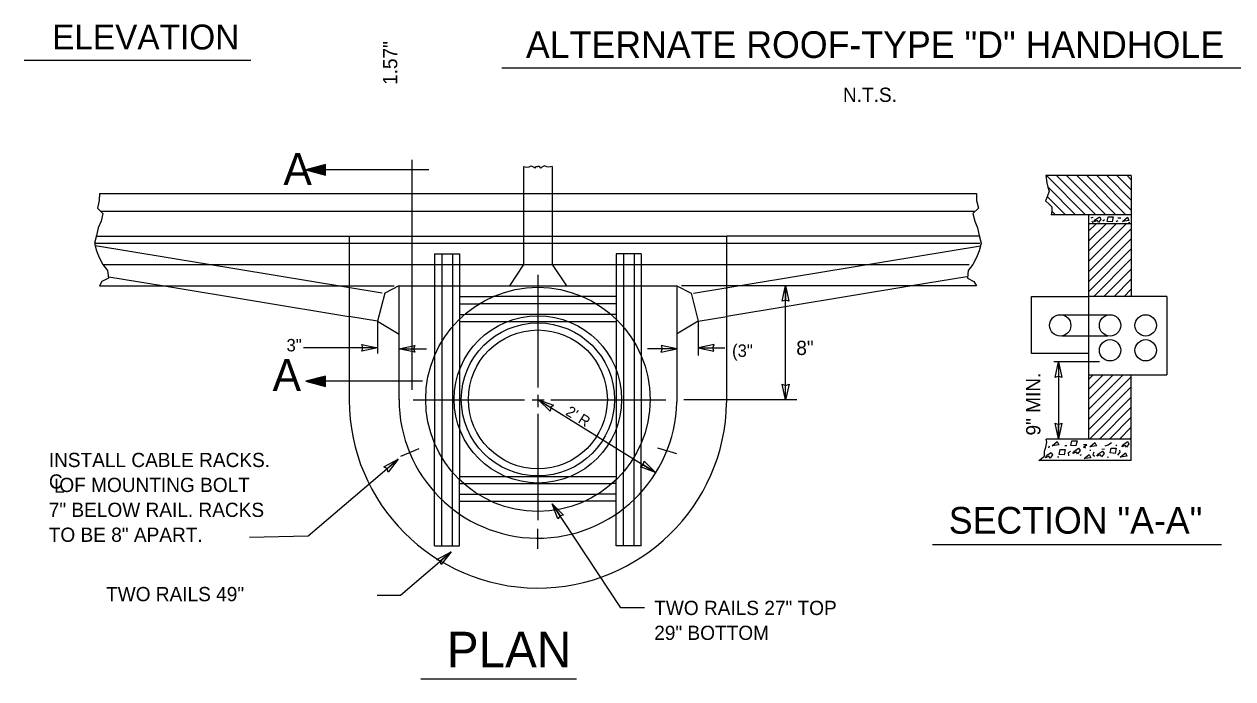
# Model space of a CAD drawing. Extents: x 19188 to 19495, y 20866 to 21061.
# Drawn here: x 19296.4 to 19367.5, y 20974.8 to 21013.4 of the extents above; entities that cross this region are included whole.
import ezdxf

# ---------------------------------------------------------------- set-up
doc = ezdxf.new("R2010")
doc.units = 0
doc.layers.add('G-ANNO-NOTE', color=7, linetype='Continuous')

msp = doc.modelspace()

# ---------------------------------------------------------------- linework, layer by layer
at = {"layer": 'G-ANNO-NOTE'}
for p, q in [((19296.432, 21011.256), (19309.768, 21011.256)), ((19324.516, 21010.791), (19369.32, 21010.791)), ((19319.253, 20991.839), (19319.253, 21005.377)), ((19320.227, 21004.804), (19313.006, 21004.804)), ((19314.124, 21004.55), (19314.124, 21005.015)), ((19325.807, 21005.001), (19325.807, 20999.217)), ((19327.483, 21005.001), (19327.483, 20999.217)), ((19361.548, 21004.454), (19356.52, 21004.454)), ((19356.557, 21004.454), (19358.861, 21002.149)), ((19357.149, 21004.454), (19359.454, 21002.149)), ((19357.742, 21004.454), (19360.046, 21002.149)), ((19358.335, 21004.454), (19360.639, 21002.149)), ((19358.927, 21004.454), (19361.231, 21002.149)), ((19359.52, 21004.454), (19361.548, 21002.425)), ((19360.112, 21004.454), (19361.548, 21003.018)), ((19360.704, 21004.454), (19361.548, 21003.61)), ((19361.297, 21004.454), (19361.548, 21004.202)), ((19361.548, 21004.454), (19361.548, 20997.331)), ((19300.854, 21003.406), (19352.435, 21003.406)), ((19356.595, 21003.231), (19357.676, 21002.149)), ((19356.649, 21003.769), (19358.269, 21002.149)), ((19300.961, 21002.359), (19352.321, 21002.359)), ((19361.548, 21002.149), (19356.825, 21002.149)), ((19356.871, 21002.362), (19357.084, 21002.149)), ((19359.034, 21002.149), (19359.034, 20988.953)), ((19359.192, 21001.98), (19359.313, 21002.008)), ((19359.223, 21001.786), (19359.282, 21001.674)), ((19359.343, 21001.73), (19359.432, 21001.869)), ((19359.552, 21001.813), (19359.343, 21001.73)), ((19359.432, 21001.869), (19359.672, 21002.036)), ((19359.612, 21001.702), (19359.552, 21001.813)), ((19359.762, 21001.897), (19359.612, 21001.702)), ((19359.672, 21002.036), (19359.762, 21001.897)), ((19359.882, 21001.786), (19359.972, 21001.869)), ((19360.122, 21001.758), (19360.181, 21002.036)), ((19360.421, 21001.73), (19360.122, 21001.758)), ((19360.181, 21002.036), (19360.481, 21002.036)), ((19360.481, 21002.036), (19360.421, 21001.73)), ((19360.661, 21001.758), (19360.751, 21001.813)), ((19360.751, 21001.98), (19360.93, 21001.98)), ((19361.02, 21001.758), (19361.32, 21002.008)), ((19361.41, 21001.813), (19361.02, 21001.758)), ((19361.32, 21002.008), (19361.41, 21001.813)), ((19361.38, 21001.702), (19361.47, 21001.702)), ((19361.548, 21001.626), (19359.034, 21001.626)), ((19359.035, 21001.183), (19359.477, 21001.626)), ((19359.037, 21000.593), (19360.07, 21001.626)), ((19359.038, 21000.001), (19360.662, 21001.626)), ((19359.039, 20999.41), (19361.254, 21001.626)), ((19359.04, 20998.819), (19361.548, 21001.326)), ((19300.601, 21000.474), (19352.63, 21000.474)), ((19317.485, 20997.539), (19300.621, 21000.325)), ((19300.696, 21000.893), (19315.529, 21000.893)), ((19315.543, 21000.893), (19315.543, 20991.257)), ((19315.543, 21000.893), (19337.746, 21000.893)), ((19335.804, 20997.539), (19352.668, 21000.325)), ((19337.746, 21000.893), (19337.746, 20991.106)), ((19352.593, 21000.893), (19337.761, 21000.893)), ((19359.042, 20998.228), (19361.548, 21000.734)), ((19320.57, 20999.846), (19320.57, 20993.853)), ((19320.57, 20999.846), (19322.036, 20999.846)), ((19320.989, 20999.846), (19320.989, 20994.689)), ((19321.618, 20999.846), (19321.618, 20995.543)), ((19322.036, 20999.846), (19322.036, 20995.988)), ((19332.719, 20999.846), (19331.253, 20999.846)), ((19331.253, 20999.846), (19331.253, 20995.988)), ((19331.672, 20999.846), (19331.672, 20995.524)), ((19332.3, 20999.846), (19332.3, 20994.651)), ((19332.719, 20999.846), (19332.719, 20993.816)), ((19359.043, 20997.637), (19361.548, 21000.141)), ((19359.322, 20997.323), (19361.548, 20999.549)), ((19301.08, 20999.217), (19352.013, 20999.217)), ((19325.807, 20999.217), (19324.969, 20997.96)), ((19327.483, 20999.217), (19328.321, 20997.96)), ((19359.916, 20997.325), (19361.548, 20998.956)), ((19301.42, 20998.495), (19304.66, 20997.96)), ((19351.87, 20998.495), (19348.629, 20997.96)), ((19360.511, 20997.327), (19361.548, 20998.364)), ((19300.854, 20997.96), (19318.198, 20997.96)), ((19304.658, 20997.96), (19315.524, 20996.165)), ((19317.638, 20997.541), (19317.212, 20995.886)), ((19318.476, 20997.96), (19317.638, 20997.541)), ((19318.476, 20997.96), (19318.476, 20991.257)), ((19318.476, 20997.96), (19334.814, 20997.96)), ((19334.814, 20997.96), (19335.652, 20997.541)), ((19334.814, 20997.96), (19334.814, 20991.131)), ((19352.435, 20997.96), (19335.091, 20997.96)), ((19335.652, 20997.541), (19336.078, 20995.886)), ((19348.631, 20997.96), (19337.765, 20996.165)), ((19341.212, 20991.257), (19341.212, 20997.987)), ((19341.212, 20997.987), (19341.212, 20997.134)), ((19361.106, 20997.33), (19361.548, 20997.772)), ((19322.036, 20997.332), (19324.018, 20997.332)), ((19322.036, 20996.913), (19323.197, 20996.913)), ((19330.059, 20996.913), (19323.197, 20996.913)), ((19329.299, 20997.332), (19324.018, 20997.332)), ((19331.253, 20997.332), (19329.299, 20997.332)), ((19331.253, 20996.913), (19330.079, 20996.913)), ((19355.682, 20993.98), (19355.682, 20997.331)), ((19355.682, 20997.331), (19359.043, 20997.331)), ((19363.642, 20997.331), (19359.043, 20997.331)), ((19363.642, 20997.331), (19363.642, 20992.723)), ((19317.212, 20995.886), (19315.533, 20996.163)), ((19322.036, 20996.284), (19322.317, 20996.284)), ((19322.036, 20995.988), (19322.036, 20986.556)), ((19330.919, 20996.284), (19322.357, 20996.284)), ((19331.253, 20996.284), (19330.919, 20996.284)), ((19331.253, 20995.988), (19331.253, 20986.574)), ((19336.078, 20995.886), (19337.756, 20996.163)), ((19357.454, 20996.257), (19360.15, 20996.257)), ((19317.212, 20995.886), (19318.489, 20995.132)), ((19317.212, 20995.886), (19317.212, 20993.984)), ((19321.618, 20995.543), (19321.618, 20987.02)), ((19322.036, 20995.866), (19331.253, 20995.866)), ((19331.672, 20995.524), (19331.672, 20987.001)), ((19336.078, 20995.886), (19334.801, 20995.132)), ((19336.078, 20995.886), (19336.078, 20993.867)), ((19320.989, 20994.689), (19320.989, 20987.892)), ((19332.3, 20994.651), (19332.3, 20987.855)), ((19357.468, 20995.022), (19360.176, 20995.022)), ((19317.212, 20994.318), (19312.868, 20994.318)), ((19317.212, 20994.318), (19316.359, 20994.318)), ((19318.476, 20994.268), (19320.104, 20994.268)), ((19318.476, 20994.268), (19319.329, 20994.268)), ((19320.57, 20993.853), (19320.57, 20988.709)), ((19334.814, 20994.268), (19333.083, 20994.268)), ((19334.814, 20994.268), (19333.961, 20994.268)), ((19336.078, 20994.318), (19337.632, 20994.318)), ((19336.078, 20994.318), (19336.93, 20994.318)), ((19359.034, 20993.98), (19355.682, 20993.98)), ((19332.719, 20993.816), (19332.719, 20988.691)), ((19359.668, 20993.501), (19356.986, 20993.501)), ((19357.266, 20993.501), (19357.266, 20988.956)), ((19357.266, 20993.501), (19357.266, 20992.648)), ((19314.124, 20992.102), (19314.124, 20992.566)), ((19359.034, 20992.723), (19363.642, 20992.723)), ((19359.034, 20990.685), (19361.072, 20992.723)), ((19359.034, 20991.278), (19360.48, 20992.723)), ((19359.034, 20991.87), (19359.887, 20992.723)), ((19359.034, 20992.462), (19359.295, 20992.723)), ((19359.034, 20990.093), (19361.548, 20992.606)), ((19361.548, 20987.696), (19361.548, 20992.723)), ((19319.857, 20992.355), (19313.006, 20992.355)), ((19341.212, 20991.257), (19341.212, 20992.111)), ((19359.034, 20989.501), (19361.548, 20992.014)), ((19326.679, 20991.261), (19327.403, 20990.811)), ((19326.746, 20991.223), (19333.569, 20986.99)), ((19341.878, 20991.257), (19335.225, 20991.257)), ((19359.079, 20988.953), (19361.548, 20991.422)), ((19359.672, 20988.953), (19361.548, 20990.829)), ((19357.266, 20988.956), (19357.266, 20989.809)), ((19360.264, 20988.953), (19361.548, 20990.237)), ((19360.856, 20988.953), (19361.548, 20989.644)), ((19361.548, 20988.953), (19356.548, 20988.953)), ((19361.449, 20988.953), (19361.548, 20989.051)), ((19318.584, 20987.934), (19319.664, 20988.386)), ((19320.57, 20982.67), (19320.57, 20988.709)), ((19332.719, 20982.67), (19332.719, 20988.691)), ((19333.673, 20988.44), (19334.793, 20988.102)), ((19356.586, 20987.992), (19356.825, 20988.159)), ((19356.706, 20988.437), (19356.736, 20988.548)), ((19356.825, 20988.159), (19356.915, 20988.02)), ((19356.886, 20988.548), (19357.185, 20988.799)), ((19357.275, 20988.604), (19356.886, 20988.548)), ((19357.185, 20988.799), (19357.275, 20988.604)), ((19357.305, 20988.047), (19357.365, 20988.326)), ((19357.365, 20988.326), (19357.665, 20988.326)), ((19357.665, 20988.326), (19357.605, 20988.02)), ((19357.634, 20988.576), (19357.754, 20988.576)), ((19357.844, 20988.159), (19357.964, 20988.242)), ((19357.874, 20987.964), (19357.844, 20988.159)), ((19357.994, 20988.576), (19358.054, 20988.854)), ((19358.294, 20988.548), (19357.994, 20988.576)), ((19358.054, 20988.854), (19358.354, 20988.854)), ((19358.114, 20988.103), (19358.204, 20988.242)), ((19358.324, 20988.187), (19358.114, 20988.103)), ((19358.204, 20988.242), (19358.444, 20988.409)), ((19358.354, 20988.854), (19358.294, 20988.548)), ((19358.384, 20988.075), (19358.324, 20988.187)), ((19358.534, 20988.27), (19358.384, 20988.075)), ((19358.444, 20988.409), (19358.534, 20988.27)), ((19358.743, 20988.465), (19358.923, 20988.604)), ((19358.923, 20988.604), (19358.743, 20988.604)), ((19358.863, 20988.409), (19358.743, 20988.465)), ((19359.103, 20988.493), (19359.403, 20988.743)), ((19359.492, 20988.548), (19359.103, 20988.493)), ((19359.103, 20988.298), (19359.163, 20988.298)), ((19359.343, 20988.187), (19359.282, 20988.02)), ((19359.403, 20988.743), (19359.492, 20988.548)), ((19359.612, 20988.075), (19359.852, 20988.242)), ((19359.822, 20988.353), (19359.972, 20988.381)), ((19359.852, 20988.242), (19359.942, 20988.103)), ((19360.001, 20988.548), (19360.181, 20988.604)), ((19360.181, 20988.604), (19360.391, 20988.743)), ((19360.301, 20988.131), (19360.361, 20988.409)), ((19360.361, 20988.409), (19360.661, 20988.409)), ((19360.661, 20988.409), (19360.601, 20988.103)), ((19360.661, 20988.548), (19360.691, 20988.604)), ((19360.751, 20987.992), (19360.901, 20988.187)), ((19360.901, 20988.187), (19360.87, 20988.298)), ((19360.991, 20988.493), (19361.08, 20988.631)), ((19361.2, 20988.576), (19360.991, 20988.493)), ((19361.08, 20988.631), (19361.32, 20988.799)), ((19361.26, 20988.465), (19361.2, 20988.576)), ((19361.41, 20988.659), (19361.26, 20988.465)), ((19361.32, 20988.799), (19361.41, 20988.659)), ((19313.138, 20983.253), (19318.425, 20987.757)), ((19318.425, 20987.757), (19317.776, 20987.204)), ((19320.989, 20982.67), (19320.989, 20987.874)), ((19332.3, 20982.67), (19332.3, 20987.855)), ((19361.548, 20987.696), (19356.102, 20987.696)), ((19356.496, 20987.853), (19356.586, 20987.992)), ((19356.706, 20987.936), (19356.496, 20987.853)), ((19356.766, 20987.825), (19356.706, 20987.936)), ((19356.915, 20988.02), (19356.766, 20987.825)), ((19357.215, 20987.908), (19357.275, 20987.908)), ((19357.605, 20988.02), (19357.305, 20988.047)), ((19358.534, 20987.992), (19358.624, 20988.047)), ((19358.773, 20987.797), (19359.073, 20988.047)), ((19359.163, 20987.853), (19358.773, 20987.797)), ((19359.073, 20988.047), (19359.163, 20987.853)), ((19359.282, 20988.02), (19359.403, 20987.936)), ((19359.522, 20987.936), (19359.612, 20988.075)), ((19359.732, 20988.02), (19359.522, 20987.936)), ((19359.792, 20987.908), (19359.732, 20988.02)), ((19359.942, 20988.103), (19359.792, 20987.908)), ((19360.122, 20987.881), (19360.211, 20987.908)), ((19360.601, 20988.103), (19360.301, 20988.131)), ((19360.901, 20987.881), (19361.2, 20988.131)), ((19361.29, 20987.936), (19360.901, 20987.881)), ((19361.2, 20988.131), (19361.29, 20987.936)), ((19321.618, 20982.67), (19321.618, 20987.02)), ((19322.036, 20986.754), (19331.253, 20986.754)), ((19331.672, 20982.67), (19331.672, 20986.982)), ((19333.569, 20986.99), (19332.844, 20987.44)), ((19322.036, 20982.67), (19322.036, 20986.556)), ((19322.036, 20986.335), (19322.297, 20986.335)), ((19322.297, 20986.335), (19330.999, 20986.335)), ((19331.253, 20986.335), (19330.999, 20986.335)), ((19331.253, 20982.67), (19331.253, 20986.574)), ((19322.036, 20985.707), (19323.137, 20985.707)), ((19323.137, 20985.707), (19330.179, 20985.707)), ((19331.253, 20985.707), (19330.199, 20985.707)), ((19322.036, 20985.288), (19323.898, 20985.288)), ((19323.938, 20985.288), (19329.359, 20985.288)), ((19331.533, 20979.019), (19327.477, 20985.136)), ((19327.477, 20985.136), (19327.948, 20984.425)), ((19331.253, 20985.288), (19329.399, 20985.288)), ((19309.686, 20983.177), (19313.138, 20983.253)), ((19326.629, 20983.656), (19326.629, 20982.485)), ((19320.57, 20982.67), (19322.036, 20982.67)), ((19332.719, 20982.67), (19331.253, 20982.67)), ((19349.849, 20982.742), (19366.846, 20982.742)), ((19318.57, 20979.758), (19321.539, 20982.312)), ((19321.539, 20982.312), (19320.892, 20981.756)), ((19317.193, 20979.758), (19318.57, 20979.758)), ((19332.909, 20979.019), (19331.533, 20979.019)), ((19319.768, 20974.836), (19328.923, 20974.836))]:
    msp.add_line(p, q, dxfattribs=at)
for points in [[(19314.16, 21004.487), (19314.16, 21005.108), (19313.006, 21004.804), (19314.16, 21004.487)], [(19314.082, 21004.567), (19314.082, 21005.033), (19313.17, 21004.805), (19314.082, 21004.567)], [(19314.043, 21004.625), (19314.043, 21004.974), (19313.312, 21004.803), (19314.043, 21004.625)], [(19314.007, 21004.673), (19314.007, 21004.936), (19313.412, 21004.807), (19314.007, 21004.673)], [(19313.978, 21004.719), (19313.978, 21004.896), (19313.515, 21004.809), (19313.978, 21004.719)], [(19313.949, 21004.762), (19313.949, 21004.86), (19313.608, 21004.813), (19313.949, 21004.762)], [(19325.807, 21005.001), (19325.991, 21004.955), (19326.123, 21004.97), (19326.246, 21005.041), (19326.413, 21004.955), (19326.465, 21004.898), (19326.544, 21004.984), (19326.641, 21004.998)], [(19327.483, 21005.001), (19327.298, 21004.955), (19327.167, 21004.97), (19327.043, 21005.041), (19326.877, 21004.955), (19326.824, 21004.898), (19326.746, 21004.984), (19326.649, 21004.998)], [(19356.52, 21004.454), (19356.584, 21004.036), (19356.631, 21003.776), (19356.716, 21003.546), (19356.593, 21003.209), (19356.509, 21002.964), (19356.707, 21002.78), (19356.867, 21002.612), (19356.867, 21002.367), (19356.825, 21002.149)], [(19300.854, 21003.406), (19300.845, 21002.983), (19300.737, 21002.532), (19301.061, 21002.231), (19300.953, 21001.781), (19300.791, 21001.38), (19300.683, 21000.929), (19300.575, 21000.478), (19300.683, 21000.027), (19300.845, 20999.627), (19301.061, 20999.226), (19301.331, 20998.875), (19301.385, 20998.424), (19301.007, 20998.225), (19300.854, 20997.96)], [(19352.435, 21003.406), (19352.444, 21002.983), (19352.552, 21002.532), (19352.229, 21002.231), (19352.337, 21001.781), (19352.498, 21001.38), (19352.606, 21000.929), (19352.714, 21000.478), (19352.606, 21000.027), (19352.444, 20999.627), (19352.229, 20999.226), (19351.959, 20998.875), (19351.905, 20998.424), (19352.283, 20998.225), (19352.435, 20997.96)], [(19326.645, 20998.617), (19326.645, 20991.991)], [(19341.212, 20997.134), (19341.008, 20997.059), (19341.212, 20997.987), (19341.407, 20997.061), (19341.212, 20997.134)], [(19316.359, 20994.318), (19316.284, 20994.522), (19317.212, 20994.318), (19316.286, 20994.123), (19316.359, 20994.318)], [(19319.329, 20994.268), (19319.403, 20994.064), (19318.476, 20994.268), (19319.401, 20994.462), (19319.329, 20994.268)], [(19333.961, 20994.268), (19333.886, 20994.064), (19334.814, 20994.268), (19333.888, 20994.462), (19333.961, 20994.268)], [(19336.93, 20994.318), (19337.005, 20994.522), (19336.078, 20994.318), (19337.003, 20994.123), (19336.93, 20994.318)], [(19357.266, 20992.648), (19357.063, 20992.573), (19357.266, 20993.501), (19357.461, 20992.575), (19357.266, 20992.648)], [(19314.16, 20992.038), (19314.16, 20992.659), (19313.006, 20992.355), (19314.16, 20992.038)], [(19314.082, 20992.118), (19314.082, 20992.584), (19313.17, 20992.356), (19314.082, 20992.118)], [(19314.043, 20992.175), (19314.043, 20992.525), (19313.312, 20992.354), (19314.043, 20992.175)], [(19314.007, 20992.224), (19314.007, 20992.486), (19313.412, 20992.358), (19314.007, 20992.224)], [(19313.978, 20992.27), (19313.978, 20992.447), (19313.515, 20992.36), (19313.978, 20992.27)], [(19313.949, 20992.313), (19313.949, 20992.412), (19313.608, 20992.363), (19313.949, 20992.313)], [(19341.212, 20992.111), (19341.416, 20992.185), (19341.212, 20991.257), (19341.017, 20992.183), (19341.212, 20992.111)], [(19319.302, 20991.257), (19325.864, 20991.257)], [(19326.31, 20991.257), (19327.022, 20991.257)], [(19326.645, 20991.546), (19326.645, 20990.833)], [(19327.403, 20990.811), (19327.359, 20990.599), (19326.679, 20991.261), (19327.568, 20990.938), (19327.403, 20990.811)], [(19327.414, 20991.257), (19329.118, 20991.257)], [(19329.118, 20991.257), (19334.176, 20991.257)], [(19326.645, 20990.442), (19326.645, 20988.8)], [(19357.266, 20989.809), (19357.47, 20989.884), (19357.266, 20988.956), (19357.072, 20989.882), (19357.266, 20989.809)], [(19356.102, 20987.696), (19356.436, 20987.936), (19356.436, 20988.242), (19356.526, 20988.465), (19356.586, 20988.771), (19356.548, 20988.953)], [(19326.645, 20988.8), (19326.645, 20984.176)], [(19317.775, 20987.204), (19317.586, 20987.31), (19318.425, 20987.757), (19317.846, 20987.008), (19317.775, 20987.204)], [(19332.844, 20987.44), (19332.889, 20987.652), (19333.569, 20986.99), (19332.68, 20987.313), (19332.844, 20987.44)], [(19327.949, 20984.425), (19327.82, 20984.249), (19327.477, 20985.136), (19328.151, 20984.471), (19327.949, 20984.425)], [(19320.892, 20981.756), (19320.703, 20981.862), (19321.539, 20982.312), (19320.964, 20981.561), (19320.892, 20981.756)]]:
    msp.add_lwpolyline(points, dxfattribs=at)
for centre, radius in [((19326.646, 20991.284), 6.598), ((19326.646, 20991.284), 4.922), ((19357.365, 20995.64), 0.628), ((19360.297, 20995.64), 0.628), ((19362.392, 20995.64), 0.628), ((19326.646, 20991.284), 4.503), ((19326.646, 20991.284), 4.085), ((19360.297, 20994.173), 0.628), ((19362.392, 20994.173), 0.628)]:
    msp.add_circle(centre, radius, dxfattribs=at)
for radius, start, end in [(11.102, 180.18569, 359.07993), (8.169, 180.05103, 358.92742)]:
    msp.add_arc((19326.646, 20991.284), radius, start, end, dxfattribs=at)

# ---------------------------------------------------------------- texts
for s, height, p in [('ELEVATION', 1.4662, (19298.078, 21011.882)), ('ALTERNATE ROOF-TYPE "D" HANDHOLE', 1.57098, (19325.942, 21011.38)), ('N.T.S.', 0.8379, (19344.588, 21008.795)), ('A', 1.885, (19311.674, 21003.898)), ('3"', 0.7331, (19311.86, 20994.109)), ('(3"', 0.7331, (19338.065, 20993.789)), ('8"', 0.8379, (19341.843, 20993.897)), ('A', 1.885, (19311.038, 20991.773)), ('INSTALL CABLE RACKS.', 0.83785, (19297.879, 20987.3)), ('C', 0.838, (19297.888, 20986.034)), ('L', 0.838, (19298.188, 20985.79)), ('  OF MOUNTING BOLT', 0.83785, (19297.879, 20985.833)), ('7" BELOW RAIL. RACKS', 0.83785, (19297.879, 20984.366)), ('SECTION "A-A"', 1.57098, (19350.811, 20983.381)), ('TO BE 8" APART.', 0.83785, (19297.879, 20982.9)), ('TWO RAILS 49"', 0.83785, (19301.25, 20979.406)), ('TWO RAILS 27" TOP', 0.83785, (19333.488, 20978.593)), ('PLAN', 2.0946, (19321.29, 20975.514)), ('29" BOTTOM', 0.8379, (19333.488, 20977.126))]:
    msp.add_text(s, height=height, dxfattribs=at).set_placement(p)
for s, height, rotation, p in [('1.57"', 0.8379, 90, (19318.376, 21009.792)), ('9" MIN.', 0.8379, 90, (19356.201, 20989.16)), ("2' R", 0.6284, 328.12523, (19328.226, 20990.405))]:
    msp.add_text(s, height=height, rotation=rotation, dxfattribs=at).set_placement(p)

doc.saveas('drawing.dxf')
